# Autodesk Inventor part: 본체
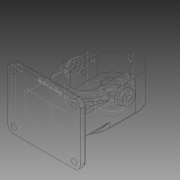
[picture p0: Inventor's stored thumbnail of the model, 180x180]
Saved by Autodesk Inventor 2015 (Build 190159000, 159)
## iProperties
Created: 2020-09
Part Number: 본체
Material: 일반
Document SubType Name: Modeling
Designer: Administrator
Density: 1 g/cm^3
Appearance: 기본값
Author: Administrator
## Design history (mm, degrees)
sketch "스케치1"
  geometry: L1 (0, 0)-(0, 44); L2 (-40, 0)-(-40, 44); L3 (40, 44)-(40, 0); A1 r 40 centre (0, 0) between (-40, 0) and (40, 0); A2 r 40 centre (0, 44) between (40, 44) and (-40, 44); 1 further point
  constraints: 8 end point, 4 point on circle, 4 tangent, 2 centre point, 1 midpoint, 1 parallel, 1 vertical
  dimensions: "d10" = 44 distance of L1.start L1.end; "d11" = 40 radius of A2
extrude "돌출1" new body sketch "스케치1" distance "d12" = 53; taper "d13" = 0 deg
sketch "스케치2"
  geometry: L1 (0, 44)-(0, 0); L2 (24, 44)-(24, 0); L3 (-24, 0)-(-24, 44); A1 r 40 centre (0, 44) between (40, 44) and (-40, 44) reference; A2 r 40 centre (0, 0) between (-40, 0) and (40, 0) reference; A3 r 24 centre (0, 44) between (24, 44) and (-24, 44); A4 r 24 centre (0, 0) between (-24, 0) and (24, 0); 2 further points
  constraints: 8 end point, 4 point on circle, 4 tangent, 2 centre point, 1 midpoint, 1 parallel, 1 vertical
  dimensions: "d14" = 24 radius of A4
extrude "돌출2" cut sketch "스케치2" distance "d15" = 29; taper "d16" = 0 deg
sketch "스케치4"
  geometry: L1 (0, 44)-(0, 0); L2 (31, 44)-(31, 0); L3 (-31, 0)-(-31, 44); L4 (0, 44)-(-31, 44); L5 (0, 44)-(31, 44); L6 (0, 0)-(0, -31); L7 (0, 0)-(31, 0); L8 (0, 0)-(-31, 0); A1 r 40 centre (0, 44) between (40, 44) and (-40, 44) reference; A2 r 40 centre (0, 0) between (-40, 0) and (40, 0) reference; A3 r 31 centre (0, 44) between (31, 44) and (-31, 44); A4 r 31 centre (0, 0) between (-31, 0) and (31, 0); A5 r 24 centre (0, 44) between (24, 44) and (-24, 44) reference; 8 further points
  constraints: 18 end point, 6 point on circle, 5 coincident, 4 horizontal, 4 tangent, 2 centre point, 1 midpoint, 1 parallel, 1 vertical
  dimensions: "d17" = 31 radius of A4
hole "구멍1" sketch "스케치4" at (0, 75), (-31, 44), (31, 44), (-31, 0), (0, -31), (31, 0) diameter "d18" = 4.134; stored, may be unused: countersink angle "d22" = 82 deg, drill point angle "d24" = 118 deg; dims "d19" = 10, "d20" = 3.023, "d21" = 2, "d23" = 12
sketch "스케치7"
  geometry: C1 r 12.5 at (0, 44); C2 r 12.5 at (0, 0); A1 r 40 centre (0, 44) between (40, 44) and (-40, 44) reference; A2 r 40 centre (0, 0) between (-40, 0) and (40, 0) reference; 1 further point
  constraints: 2 centre point, 2 coincident
  dimensions: "d25" = 25 diameter of C1; "d26" = 25 diameter of C2
extrude "돌출3" cut sketch "스케치7" distance "d27" = 15; taper "d28" = 0 deg
sketch "스케치11"
  geometry: L1 (24, 44)-(24, 0) reference; L2 (-24, 0)-(-24, 44) reference; L3 (-40, 44)-(-40, 0) reference; L4 (40, 0)-(40, 44) reference; C1 r 2.067 at (0, -31) reference; C2 r 2.067 at (31, 44) reference; C3 r 2.067 at (0, 75) reference; C4 r 2.067 at (-31, 44) reference; C5 r 2.067 at (-31, 0) reference; C6 r 2.067 at (31, 0) reference; C7 r 8.5 at (0, 44); A1 r 24 centre (0, 44) between (24, 44) and (-24, 44) reference; A2 r 24 centre (0, 0) between (-24, 0) and (24, 0) reference; A3 r 40 centre (0, 0) between (-40, 0) and (40, 0) reference; A4 r 40 centre (0, 44) between (40, 44) and (-40, 44) reference; 1 further point
  constraints: 1 centre point, 1 coincident
  dimensions: "d34" = 17 diameter of C7
extrude "돌출5" cut sketch "스케치11" distance "d35" = 34.75; taper "d36" = 0 deg
sketch "스케치12"
  geometry: L1 (40, 0)-(40, 44) reference; L2 (-40, 44)-(-40, 0) reference; C1 r 8.5 at (0, 44) reference; C2 r 19 at (0, 44); A1 r 40 centre (0, 44) between (40, 44) and (-40, 44) reference; A2 r 40 centre (0, 0) between (-40, 0) and (40, 0) reference; 1 further point
  constraints: 1 centre point, 1 coincident
  dimensions: "d37" = 38 diameter of C2
extrude "돌출6" join sketch "스케치12" distance "d38" = 17; taper "d39" = 0 deg
sketch "스케치13"
  geometry: L1 (40, -44)-(40, 0) reference; L2 (-40, 0)-(-40, -44) reference; C1 r 19 at (0, 0) reference; C2 r 14 at (0, 0); A1 r 40 centre (0, 0) between (40, 0) and (-40, 0) reference; A2 r 40 centre (0, -44) between (-40, -44) and (40, -44) reference; 1 further point
  constraints: 1 centre point, 1 coincident
  dimensions: "d40" = 28 diameter of C2
extrude "돌출7" cut sketch "스케치13" distance "d41" = 7.3; taper "d42" = 0 deg
sketch "스케치14"
  geometry: L1 (0, 44)-(0, 0) reference; L2 (0, 44)-(-53, 44) reference; L3 (-53, 0)-(-53, 44) reference; L4 (0, 0)-(-53, 0) reference; L5 (-53, 44)-(-53, 0) reference; L6 (-53, 22)-(-39, 22); C1 r 11 at (-39, 22); 1 further point
  constraints: 2 end point, 1 centre point, 1 coincident, 1 horizontal, 1 midpoint
  dimensions: "d43" = 14 distance of L6.start L6.end; "d44" = 22 diameter of C1
extrude "돌출8" join sketch "스케치14" distance "d45" = 10; taper "d46" = 0 deg
node "스케치15"
sketch "스케치16"
  geometry: L1 (0, 0)-(0, 44) reference; L2 (0, 0)-(53, 0) reference; L3 (53, 44)-(53, 0) reference; L4 (0, 44)-(53, 44) reference; L5 (53, 44)-(53, 0) reference; L6 (53, 22)-(39, 22); C1 r 11 at (39, 22); 1 further point
  constraints: 2 end point, 1 centre point, 1 coincident, 1 horizontal, 1 midpoint
  dimensions: "d47" = 14 distance of L6.start L6.end; "d48" = 22 diameter of C1
extrude "돌출9" join sketch "스케치16" distance "d49" = 10; taper "d50" = 0 deg
sketch "스케치17"
  geometry: C1 r 11 at (0, 0) reference; 2 further points
  constraints: 1 coincident
hole "구멍2" sketch "스케치17" at (0, 0) diameter "d51" = 8.376; stored, may be unused: countersink angle "d55" = 90 deg, drill point angle "d57" = 118 deg; dims "d52" = 20, "d53" = 4, "d54" = 2, "d56" = 27.3
node "작업 평면2"
  node "작업 평면1"
sketch "스케치18"
  geometry: L1 (16, -53)-(-64, -53) reference; L2 (16, -53)-(16, 0) reference; L3 (-64, 0)-(16, 0) reference; L4 (-64, -53)-(-64, 0) reference; L5 (26, -70)-(-74, -70); L6 (-84, -60)-(-84, 20); L7 (-74, 30)-(26, 30); L8 (36, 20)-(36, -60); L9 (-43, -70)-(-5, -70) reference; A1 r 10 centre (-74, 20) between (-74, 30) and (-84, 20); A2 r 10 centre (26, 20) between (36, 20) and (26, 30); A3 r 10 centre (26, -60) between (26, -70) and (36, -60); A4 r 10 centre (-74, -60) between (-84, -60) and (-74, -70); 1 further point
  constraints: 10 tangent, 8 end point, 8 point on circle, 4 centre point, 3 equal radius, 2 midpoint, 2 parallel, 1 horizontal, 1 perpendicular
  dimensions: "d61" = 10 radius of A1; "d64" = 30 distance between parallel lines of L3 L7
extrude "돌출10" join sketch "스케치18" distance "d65" = 10; taper "d66" = 0 deg
fillet "모깎기1" dims "d67" = 3
sketch "스케치19"
  geometry: L1 (84, -20)-(84, 60) reference; L2 (-26, -30)-(74, -30) reference; L3 (-36, 60)-(-36, -20) reference; L4 (74, 70)-(-26, 70) reference; C1 r 4.5 at (-26, -20); C2 r 4.5 at (-26, 60); C3 r 4.5 at (74, 60); C4 r 4.5 at (74, -20); A1 r 10 centre (74, -20) between (74, -30) and (84, -20) reference; A2 r 10 centre (-26, -20) between (-36, -20) and (-26, -30) reference; A3 r 10 centre (-26, 60) between (-26, 70) and (-36, 60) reference; A4 r 10 centre (74, 60) between (84, 60) and (74, 70) reference; 1 further point
  constraints: 4 centre point, 4 coincident
  dimensions: "d68" = 9 diameter of C1; "d69" = 9 diameter of C2; "d70" = 9 diameter of C3; "d71" = 9 diameter of C4
extrude "돌출11" cut sketch "스케치19" distance "d72" = 10; taper "d73" = 0 deg
node "작업 평면3"
sketch "스케치20"
  geometry: L1 (10, 68)-(10, 10); L2 (0, 10)-(100, 10) reference; L3 (90, 68)-(90, 10); L4 (10, 10)-(90, 10); A1 r 40 centre (50, 68) between (10, 68) and (90, 68); 1 further point
  constraints: 6 end point, 2 point on circle, 2 point on line, 1 centre point, 1 collinear, 1 perpendicular, 1 vertical
  dimensions: "d75" = 40 radius of A1
extrude "돌출12" join sketch "스케치20" distance "d76" = 37; taper "d77" = 0 deg
sketch "스케치21"
  geometry: A1 r 10 centre (-26, -20) between (-36, -20) and (-26, -30) reference; 2 further points
  constraints: 1 other
  dimensions: "d78" = 12 vertical distance of A1.end point (24, -18); "d79" = 60 horizontal distance of A1.start point (24, -18)
feature "엠보싱1" sketch "스케치21" dims "d10" = 44, "d11" = 40, "d80" = 0.5, "d81" = 0
fillet "모깎기2" dims "d82" = 3
fillet "모깎기3" dims "d83" = 3
chamfer "모따기1" distance "d84" = 1; stored, may be unused: second distance "d85" = 2, angle "d86" = 45 deg
fillet "모깎기4" dims "d87" = 0.5
node "솔리드1"
node "투영된 루프2"
node "투영된 루프3"
node "투영된 루프4"
node "투영된 루프5"
node "투영된 루프6"
node "투영된 루프7"
node "투영된 루프8"
node "투영된 루프9"
other parameters: "d74" = -62
